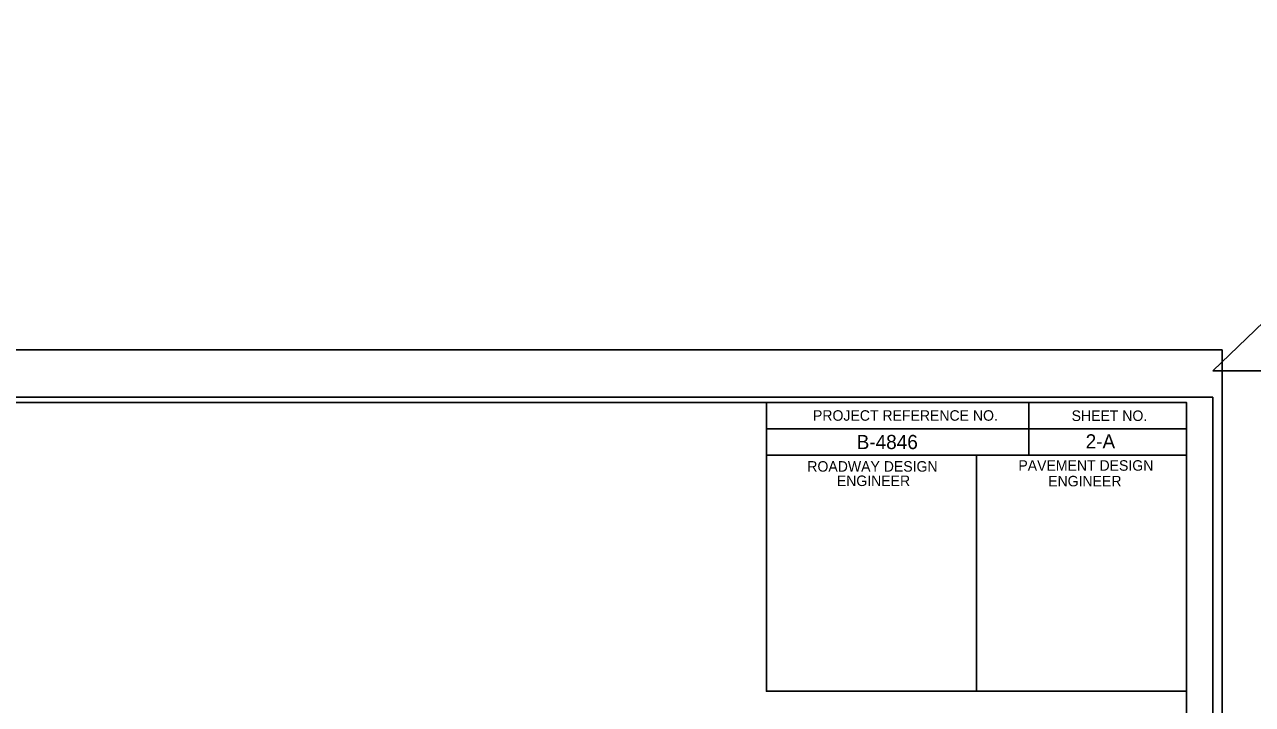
# Model space of a CAD drawing. Extents: x 1542177 to 1542464, y 45134 to 45344.
# Drawn here: x 1542315.1 to 1542361.88, y 45208.94 to 45234.85 of the extents above; entities that cross this region are included whole.
import ezdxf

# ---------------------------------------------------------------- set-up
doc = ezdxf.new("R2010")
doc.units = 0
for name, color, linetype in [('Default', 7, 'Continuous'), ('Sheet Cutting Line CELL', 7, 'Continuous'), ('Sheet Data Field CELL', 7, 'Continuous'), ('Sheet Plot Border Inside CELL', 7, 'Continuous'), ('Sheet Plot Border Outside CELL', 7, 'Continuous'), ('Sheet Typical CELL', 7, 'Continuous')]:
    doc.layers.add(name, color=color, linetype=linetype)

msp = doc.modelspace()

# ---------------------------------------------------------------- linework, layer by layer
at = {"layer": 'Default'}
for q in [(1542374.107, 45234.847), (1542365.968, 45221.652)]:
    msp.add_line((1542360.367, 45221.652), q, dxfattribs=at)
at = {"layer": 'Sheet Cutting Line CELL'}
msp.add_line((1542360.727, 45222.448), (1542226.007, 45222.448), dxfattribs=at)
at = {"layer": 'Sheet Plot Border Inside CELL'}
msp.add_lwpolyline([(1542360.367, 45220.652), (1542227.047, 45220.652), (1542227.047, 45136.244), (1542360.367, 45136.244)], close=True, dxfattribs=at)
at = {"layer": 'Sheet Plot Border Outside CELL'}
msp.add_lwpolyline([(1542360.727, 45222.448), (1542226.007, 45222.448), (1542226.007, 45134.448), (1542360.727, 45134.448)], close=True, dxfattribs=at)
at = {"layer": 'Sheet Typical CELL'}
for p, q in [((1542353.367, 45220.444), (1542353.367, 45218.444)), ((1542343.363, 45219.444), (1542359.367, 45219.444)), ((1542351.367, 45218.444), (1542351.367, 45209.448))]:
    msp.add_line(p, q, dxfattribs=at)
for points in [[(1542359.367, 45220.448), (1542239.367, 45220.448), (1542239.367, 45136.448), (1542359.367, 45136.448)], [(1542343.363, 45220.448), (1542359.367, 45220.448), (1542359.367, 45218.444), (1542343.363, 45218.444)], [(1542343.363, 45218.444), (1542351.367, 45218.444), (1542351.367, 45209.444), (1542343.363, 45209.444)], [(1542351.367, 45218.444), (1542359.367, 45218.444), (1542359.367, 45209.444), (1542351.367, 45209.444)]]:
    msp.add_lwpolyline(points, close=True, dxfattribs=at)

# ---------------------------------------------------------------- texts
at = {"layer": 'Sheet Data Field CELL'}
for s, p in [('B-4846', (1542346.804, 45218.672)), ('2-A', (1542355.527, 45218.696))]:
    msp.add_text(s, height=0.54, dxfattribs=at).set_placement(p)
at = {"layer": 'Sheet Typical CELL'}
for s, height, p in [('PROJECT REFERENCE NO.', 0.40001, (1542345.139, 45219.752)), ('SHEET NO.', 0.4, (1542354.991, 45219.744)), ('PAVEMENT DESIGN', 0.40001, (1542352.963, 45217.848)), ('ROADWAY DESIGN', 0.40001, (1542344.923, 45217.812)), ('ENGINEER', 0.4, (1542346.047, 45217.264)), ('ENGINEER', 0.4, (1542354.099, 45217.252))]:
    msp.add_text(s, height=height, dxfattribs=at).set_placement(p)

doc.saveas('drawing.dxf')
